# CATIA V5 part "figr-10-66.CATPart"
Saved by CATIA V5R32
Part number: Part1
Bounding box of the stored display mesh (mm): x -80.563 to 63.541, y -72 to 69, z -55 to 56
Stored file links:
  D:\PROJECTS\Project 2022\CATIA V5 6R 2022\Resources\Part Files\c10_catia_v5_6r2022_prt\c10_catia_v5_6r2022_prt\figr-10-66.CATPart
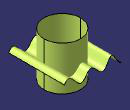
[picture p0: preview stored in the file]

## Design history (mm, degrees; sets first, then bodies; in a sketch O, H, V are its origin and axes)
Set1
  Sketch1 on xy-plane, origin (0, 0, 0), H (-1, 0, 0), V (0, -1, 0)
    circle A1 centre (0, 0) radius 45.985
  Extrude1: Element1 Sketch1, Lim1 56, Lim2 55, Direction xy-plane
  Sketch2 on zx-plane, origin (0, 0, 0), H (1, 0, 0), V (0, 0, -1)
    spline S1 through (-80.5635, 24.8913) (-73.6025, 19.8803) (-54.8525, -3.3629) (-35.1982, 19.8803) (-2.6271, -1.6506) (16.6996, 17.2854) (52.4104, -6.7877) (63.5409, 1.5862)
  Extrude2: Element1 Sketch2, Lim1 72, Lim2 69, Direction Sketch1.V
Body1 (main body)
